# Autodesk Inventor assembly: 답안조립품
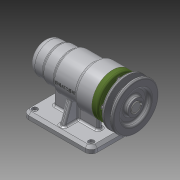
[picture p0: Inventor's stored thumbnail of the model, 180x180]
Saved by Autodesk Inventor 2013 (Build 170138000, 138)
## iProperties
Created: 2016-06
Part Number: 답안조립품
Document SubType Name: Assembly
Designer: Administrator
Author: Administrator
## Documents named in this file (12)
- C:\Users\Administrator\Desktop\460607V1009\답안조립품.iam
- C:\Users\Administrator\Desktop\460607V1009\본체.ipt
- C:\Users\Administrator\Desktop\460607V1009\V벨트풀리.ipt
- C:\Users\Administrator\Desktop\460607V1009\멈춤나사 M3x8.ipt
- C:\Users\Administrator\Desktop\460607V1009\베어링 6004.ipt
- C:\Users\Administrator\Desktop\460607V1009\베어링 51202.ipt
- C:\Users\Administrator\Desktop\460607V1009\볼트 M4 x 12.ipt
- C:\Users\Administrator\Desktop\460607V1009\어댑터슬리브.ipt
- C:\Users\Administrator\Desktop\460607V1009\오일 실.ipt
- C:\Users\Administrator\Desktop\460607V1009\축.ipt
- C:\Users\Administrator\Desktop\460607V1009\커버.ipt
- C:\Users\Administrator\Desktop\460607V1009\키 5 x 5 x 16.ipt
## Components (6 placed, 2 different names)
1. V벨트풀리:1
2. ISO 4762 M4 x 12:1
3. ISO 4762 M4 x 12:2
4. ISO 4762 M4 x 12:3
5. ISO 4762 M4 x 12:4
6. ISO 4762 M4 x 12:5
